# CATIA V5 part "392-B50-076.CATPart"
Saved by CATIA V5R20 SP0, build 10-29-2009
Part number: 392-B50-076
Definition: NONE
Nomenclature: 392-B50-076
Source: Unknown
Description: 392-B50-076
Bounding box of the stored display mesh (mm): x 0 to 76, y -24.566 to 24.566, z -24.4 to 24.222
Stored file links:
  C:\Users\Utente\Desktop\IO LAVORO\3D X SITO CF\X SITO\3D files 392B\392-B50-076.CATPart
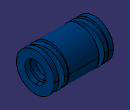
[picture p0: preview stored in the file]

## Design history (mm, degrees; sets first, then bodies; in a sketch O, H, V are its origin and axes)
Body1 "392-B50-076" (main body)
  Solid1: solid without history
